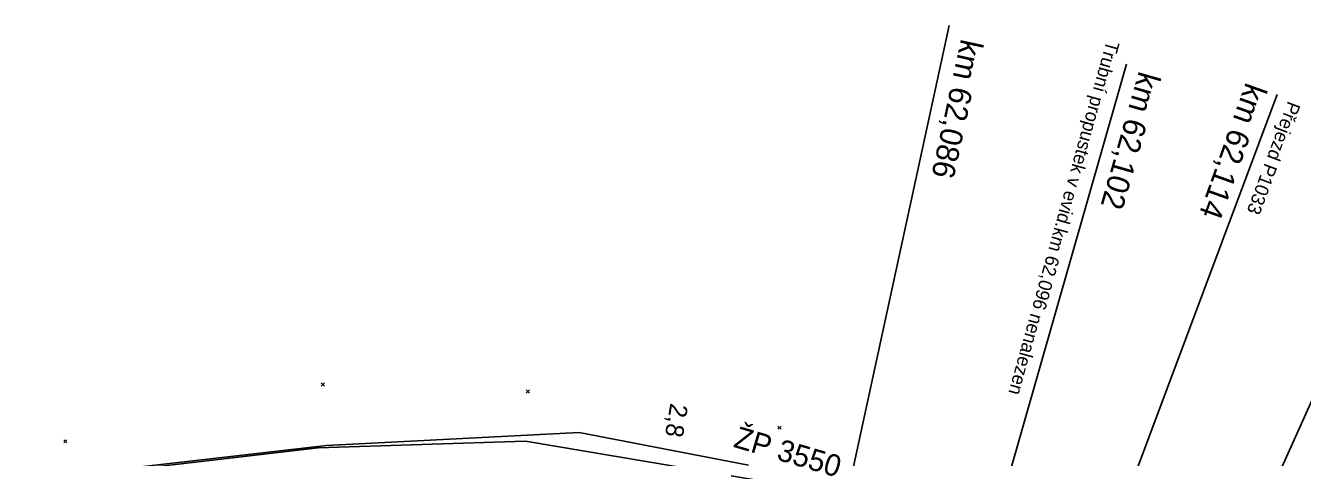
# Model space of a CAD drawing. Extents: x -805636 to -804553, y -1165340 to -1164656.
# Drawn here: x -805494.5 to -805352.6, y -1164875.5 to -1164827.5 of the extents above; entities that cross this region are included whole.
import ezdxf

# ---------------------------------------------------------------- set-up
doc = ezdxf.new("R2010")
doc.units = 0
for name, color, linetype in [('0381KM061-064P - Vrstva 19', 7, 'Continuous'), ('0381KM061-064P - Vrstva 4', 7, 'Continuous'), ('0381KM061-064P - Vrstva 48', 7, 'Continuous'), ('0381KM061-064P - Vrstva 49', 7, 'Continuous'), ('0381KM061-064P - Vrstva 8', 7, 'Continuous'), ('0381KM061-064P - Vrstva 9', 7, 'Continuous'), ('hran DP - hran DP', 7, 'Continuous'), ('vyt_sit - stávající', 7, 'Continuous')]:
    doc.layers.add(name, color=color, linetype=linetype)

msp = doc.modelspace()

# ---------------------------------------------------------------- linework, layer by layer
at = {"layer": '0381KM061-064P - Vrstva 4'}
msp.add_line((-805355.47, -1164835.15), (-805377.11, -1164893.01), dxfattribs=at)
at = {"layer": '0381KM061-064P - Vrstva 49'}
for p, q in [((-805461.3, -1164867.54), (-805461.65, -1164867.18)), ((-805461.3, -1164867.18), (-805461.65, -1164867.54)), ((-805438.52, -1164868.33), (-805438.87, -1164867.98)), ((-805438.52, -1164867.98), (-805438.87, -1164868.33)), ((-805410.56, -1164872.33), (-805410.91, -1164871.98)), ((-805410.56, -1164871.98), (-805410.91, -1164872.33)), ((-805489.9, -1164873.86), (-805490.25, -1164873.51)), ((-805489.9, -1164873.51), (-805490.25, -1164873.86))]:
    msp.add_line(p, q, dxfattribs=at)
msp.add_lwpolyline([(-805619.35, -1164890.95), (-805615.91, -1164890.53), (-805590.56, -1164886.39), (-805529.03, -1164882.21), (-805489.9, -1164877.68), (-805461.98, -1164874.39), (-805438.96, -1164873.66), (-805412.14, -1164878.2), (-805389.29, -1164884.48), (-805375.6, -1164889.14)], dxfattribs=at)
at = {"layer": '0381KM061-064P - Vrstva 8'}
for p, q in [((-805387.65, -1164885.82), (-805372.19, -1164831.77)), ((-805363.02, -1164894.54), (-805338.8, -1164840.62))]:
    msp.add_line(p, q, dxfattribs=at)
at = {"layer": '0381KM061-064P - Vrstva 9'}
msp.add_line((-805403.65, -1164881.66), (-805391.9, -1164827.49), dxfattribs=at)
at = {"layer": 'hran DP - hran DP'}
for p, q in [((-805461.06, -1164874.13), (-805433.01, -1164872.7)), ((-805433.01, -1164872.7), (-805414.19, -1164876.33)), ((-805493.02, -1164877.83), (-805461.06, -1164874.13))]:
    msp.add_line(p, q, dxfattribs=at)

# ---------------------------------------------------------------- texts
at = {"layer": '0381KM061-064P - Vrstva 19'}
msp.add_text('Trubní propustek v evid.km 62,096 nenalezen', height=1.5, rotation=254.4208, dxfattribs=at).set_placement((-805374.39, -1164829.09))
at = {"layer": '0381KM061-064P - Vrstva 4'}
for s, height, rotation, p in [('km 62,114', 2.5, 250.3868, (-805358.91, -1164833.71)), ('Přejezd P1033', 1.5, 249.4891, (-805354.24, -1164835.8))]:
    msp.add_text(s, height=height, rotation=rotation, dxfattribs=at).set_placement(p)
at = {"layer": '0381KM061-064P - Vrstva 48'}
msp.add_text('2,8', height=2, rotation=260.3835, dxfattribs=at).set_placement((-805422.85, -1164869.38))
at = {"layer": '0381KM061-064P - Vrstva 8'}
msp.add_text('km 62,102', height=2.5, rotation=254.036, dxfattribs=at).set_placement((-805370.79, -1164832.46))
at = {"layer": '0381KM061-064P - Vrstva 9'}
msp.add_text('km 62,086', height=2.5, rotation=257.7697, dxfattribs=at).set_placement((-805390.56, -1164828.89))
at = {"layer": 'vyt_sit - stávající'}
msp.add_text('ŽP 3550', height=2.4, rotation=343.5611, dxfattribs=at).set_placement((-805415.96, -1164874.28))

doc.saveas('drawing.dxf')
